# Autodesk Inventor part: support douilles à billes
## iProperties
Shininess: 64.0
Length Units: 11269
Angle Units: 11279
Time Units: 11290
Mass Units: 11283
Length Display Precision: 3
Angle Display Precision: 2
Compacted: True
Part Number: support douilles à billes
Document SubType Name: Modeling
Created: 2005-01
Material: Par défaut
Designer: LEGERET Philippe
Density: 0.0
Volumn: 0.0
Area: 0.0
PropertySet Name: Model Information
Control State: 0
Master: False
Checked Out: False
Author: LEGERET Philippe
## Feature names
1. Extrusion1
2. Perçage1 [Hole]
